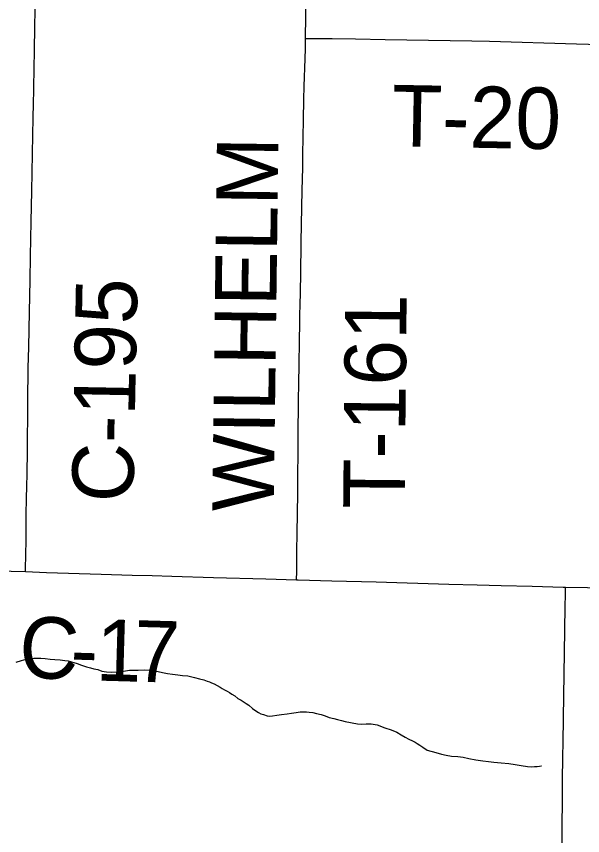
# Model space of a CAD drawing. Extents: x 0 to 34, y 0 to 22.
# Drawn here: x 26.263 to 26.787, y 15.137 to 15.894 of the extents above; entities that cross this region are included whole.
import ezdxf

# ---------------------------------------------------------------- set-up
doc = ezdxf.new("R2010")
doc.units = 0
for name, color, linetype in [('GM_X_County_Road', 7, 'Continuous'), ('GM_X_County_Road_Text', 7, 'Continuous'), ('GM_X_Minor_River', 7, 'Continuous'), ('GM_X_Township_Road', 7, 'Continuous'), ('GM_X_Township_Road_Text', 7, 'Continuous')]:
    doc.layers.add(name, color=color, linetype=linetype)

msp = doc.modelspace()

# ---------------------------------------------------------------- linework, layer by layer
at = {"layer": 'GM_X_County_Road'}
for points in [[(26.27184, 15.38099), (26.27212, 15.39898), (26.27231, 15.40766), (26.2724, 15.41697), (26.27242, 15.42381), (26.27251, 15.43562), (26.27276, 15.44681), (26.27308, 15.46172), (26.27316, 15.46918), (26.27355, 15.49466), (26.27365, 15.50709), (26.27386, 15.52139), (26.27395, 15.53816), (26.27433, 15.56926), (26.27482, 15.58852), (26.27543, 15.621), (26.27598, 15.65028), (26.2764, 15.67241), (26.27705, 15.70473), (26.27757, 15.7327), (26.27864, 15.78429), (26.27897, 15.80042), (26.27898, 15.8029), (26.27913, 15.81132), (26.27999, 15.86297), (26.28044, 15.88419), (26.28114, 15.91642)], [(26.24499, 15.38173), (26.27184, 15.38099)], [(26.27184, 15.38099), (26.29131, 15.38009), (26.34162, 15.37849), (26.37022, 15.37776), (26.38885, 15.37732), (26.40687, 15.37677), (26.4454, 15.37569), (26.49386, 15.37422), (26.52232, 15.37339)], [(26.52232, 15.37339), (26.52369, 15.37335), (26.55476, 15.37256), (26.59578, 15.37157), (26.66288, 15.36946), (26.68899, 15.36883), (26.71135, 15.36822), (26.73994, 15.36751), (26.76852, 15.36663), (26.7709, 15.36659)], [(26.76753, 15.1277), (26.76793, 15.18738), (26.76841, 15.21037), (26.76853, 15.22279), (26.7689, 15.24578), (26.77013, 15.32657), (26.77047, 15.34895), (26.77073, 15.35952), (26.7709, 15.36659)], [(26.7709, 15.36659), (26.81141, 15.36584), (26.82943, 15.36534), (26.85118, 15.36512), (26.8891, 15.3645), (26.96681, 15.36373), (27.00036, 15.36322), (27.01964, 15.36295), (27.06439, 15.3624), (27.10728, 15.36191), (27.14891, 15.36116), (27.19119, 15.36051), (27.21791, 15.3603), (27.26997, 15.35976)]]:
    msp.add_lwpolyline(points, dxfattribs=at)
at = {"layer": 'GM_X_Minor_River'}
for points in [[(26.26312, 15.29741), (26.26811, 15.29877), (26.27235, 15.30015), (26.27655, 15.30077), (26.27961, 15.30105), (26.28265, 15.30095), (26.28608, 15.30084), (26.28988, 15.30071), (26.29443, 15.30018), (26.29899, 15.29965), (26.30393, 15.29949), (26.30811, 15.29897), (26.31114, 15.29849), (26.31416, 15.29763), (26.31943, 15.29593), (26.32358, 15.29465), (26.3281, 15.29298), (26.33188, 15.2921), (26.3349, 15.29124), (26.33868, 15.29035), (26.34245, 15.28909), (26.34661, 15.28819), (26.35155, 15.28802), (26.35651, 15.28824), (26.36224, 15.28881), (26.36799, 15.28977), (26.37599, 15.28988), (26.38133, 15.29009), (26.38589, 15.28993), (26.39006, 15.28941), (26.39422, 15.28852), (26.39839, 15.28762), (26.40293, 15.28671), (26.40748, 15.28618), (26.41241, 15.28563), (26.41697, 15.2851), (26.4219, 15.28456), (26.42795, 15.28322), (26.43248, 15.28193), (26.43664, 15.28103), (26.43965, 15.27979), (26.4419, 15.27895), (26.44378, 15.27813), (26.44604, 15.27729)], [(26.44604, 15.27729), (26.45165, 15.27407), (26.45352, 15.27286), (26.45576, 15.27165), (26.45801, 15.27043), (26.46025, 15.26922), (26.46249, 15.26762), (26.4651, 15.26601), (26.46808, 15.26363), (26.47107, 15.26201), (26.47369, 15.2604), (26.47555, 15.2592), (26.47817, 15.25759), (26.48149, 15.25444), (26.48447, 15.25244), (26.48709, 15.25083), (26.48933, 15.24961), (26.49159, 15.24878), (26.49498, 15.24752), (26.49688, 15.24746), (26.49994, 15.24774), (26.50415, 15.24836), (26.50836, 15.24898), (26.51371, 15.24957), (26.51754, 15.2502), (26.52175, 15.25082), (26.52557, 15.25146), (26.52824, 15.25137), (26.53128, 15.25127), (26.53394, 15.25118), (26.53735, 15.25069), (26.54076, 15.24981), (26.54492, 15.24892), (26.54869, 15.24765), (26.55244, 15.24601), (26.5566, 15.24511), (26.56, 15.24423), (26.56378, 15.24335), (26.56718, 15.24247), (26.57853, 15.2402), (26.58234, 15.24007), (26.58653, 15.24031), (26.5911, 15.24016), (26.59678, 15.23921), (26.60394, 15.2367), (26.60958, 15.23461), (26.61485, 15.23253), (26.61896, 15.23011), (26.62271, 15.22809), (26.62607, 15.22607), (26.62944, 15.22444), (26.63169, 15.22322), (26.63356, 15.22202), (26.63617, 15.22041), (26.63879, 15.2188), (26.64289, 15.216), (26.65081, 15.21384), (26.65609, 15.21214), (26.66063, 15.21123), (26.66556, 15.21031), (26.67126, 15.21012), (26.6762, 15.20958), (26.68149, 15.20826), (26.68792, 15.20691), (26.69436, 15.20593), (26.69967, 15.20538), (26.70461, 15.20484), (26.71144, 15.20423), (26.71828, 15.20362), (26.72434, 15.20266), (26.72964, 15.20173), (26.73571, 15.20076), (26.73951, 15.20064), (26.74219, 15.20093), (26.74447, 15.20085), (26.74676, 15.20116), (26.7483, 15.20149), (26.74868, 15.20148)]]:
    msp.add_lwpolyline(points, dxfattribs=at)
at = {"layer": 'GM_X_Township_Road'}
for points in [[(26.53064, 15.87372), (26.53066, 15.89438), (26.53142, 15.93144), (26.53186, 15.94966), (26.53232, 15.96931), (26.53295, 15.98483), (26.53345, 16.00164), (26.53418, 16.02647), (26.53399, 16.04176), (26.53371, 16.04604), (26.53337, 16.04933), (26.53299, 16.05135), (26.53265, 16.05265), (26.53208, 16.05395), (26.53122, 16.0553)], [(26.52232, 15.37339), (26.52241, 15.3812), (26.5226, 15.39985), (26.52278, 15.41664), (26.52331, 15.45331), (26.52381, 15.5074), (26.52412, 15.53786), (26.52432, 15.55651), (26.52461, 15.57082), (26.5248, 15.58138), (26.52495, 15.58511), (26.52529, 15.61992), (26.52546, 15.62613), (26.52606, 15.65533), (26.52664, 15.68579), (26.52754, 15.73363), (26.5279, 15.7541), (26.52801, 15.76641), (26.52865, 15.79865), (26.52902, 15.81723), (26.52939, 15.82958), (26.5301, 15.85502), (26.53046, 15.86464), (26.53064, 15.87372)], [(26.53064, 15.87372), (26.53837, 15.8738), (26.55521, 15.87364), (26.5767, 15.87332), (26.60418, 15.87292), (26.68412, 15.87152), (26.70043, 15.87129), (26.781, 15.86892), (26.83679, 15.86728), (26.86012, 15.86691), (26.88793, 15.86674), (26.95241, 15.86613), (26.99024, 15.86485), (27.01553, 15.864), (27.02544, 15.86366)]]:
    msp.add_lwpolyline(points, dxfattribs=at)

# ---------------------------------------------------------------- texts
at = {"layer": 'GM_X_County_Road_Text'}
for s, height, rotation, p in [('C-195', 0.056818, 88.91602, (26.37135, 15.44467)), ('C', 0.05682, 356.94639, (26.26474, 15.2836)), ('1', 0.05682, 358.37026, (26.3362, 15.28032)), ('7', 0.05682, 358.43236, (26.37126, 15.27933)), ('-', 0.05682, 358.20535, (26.3127, 15.28106))]:
    msp.add_text(s, height=height, rotation=rotation, dxfattribs=at).set_placement(p)
at = {"layer": 'GM_X_Township_Road_Text'}
for s, rotation, p in [('T-20', 358.95093, (26.60995, 15.77416)), ('WILHELM', 89.27115, (26.50113, 15.43622)), ('T-161', 89.44598, (26.62209, 15.43875))]:
    msp.add_text(s, height=0.056818, rotation=rotation, dxfattribs=at).set_placement(p)

doc.saveas('drawing.dxf')
